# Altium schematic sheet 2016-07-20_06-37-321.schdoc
size 220 x 113 mm; SheetNumber: 1; SheetTotal: 1
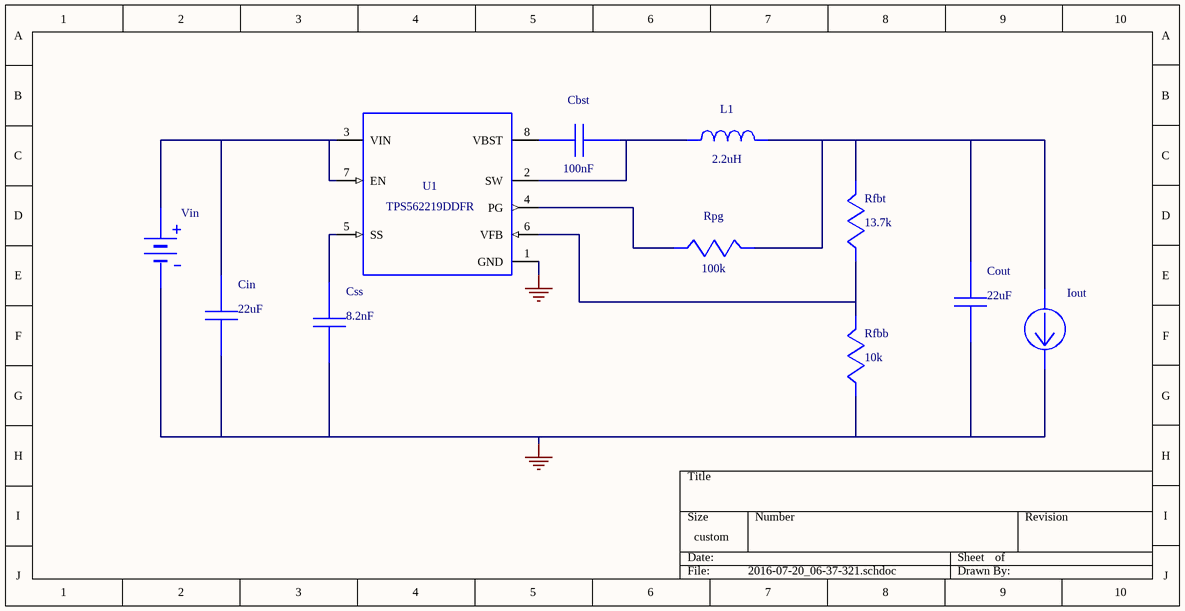
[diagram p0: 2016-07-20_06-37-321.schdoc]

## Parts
Cbst  value 100nF  (hidden comment: 08053C104KAT2A)
Cin  value 22uF  (hidden comment: GRM31CR61A226KE19L)
Cout  value 22uF  (hidden comment: GRM21BC80G226ME39L)
Css  value 8.2nF  (hidden comment: GRM033R61A822KA01D)
Iout  WB_CURRENT_LOAD  (value not drawn)
L1  value 2.2uH  (hidden comment: 'VLF403215MT-2R2M')
Rfbb  value 10k  (hidden comment: CRCW040210K0FKED)
Rfbt  value 13.7k  (hidden comment: CRCW040213K7FKED)
Rpg  value 100k  (hidden comment: CRCW0402100KFKED)
U1  TPS562219DDFR
Vin  WB_BATTERY  (value not drawn)

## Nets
0: Cin.2 Cout.2 Css.2 Iout.2(-) Rfbb.2 U1.1(GND) Vin.2(-)
NetCbst_1: Cbst.1 L1.2 U1.2(SW)
NetCbst_2: Cbst.2 U1.8(VBST)
NetCin_1: Cin.1 U1.3(VIN) U1.7(EN) Vin.1(+)
NetCout_1: Cout.1 Iout.1(+) L1.1 Rfbt.1 Rpg.1
NetCss_1: Css.1 U1.5(SS)
NetRfbb_1: Rfbb.1 Rfbt.2 U1.6(VFB)
NetRpg_2: Rpg.2 U1.4(PG)

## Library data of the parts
Cbst = 08053C104KAT2A: Manufacturer Name: AVX
Cin = GRM31CR61A226KE19L: GRM31CR61A226KE1; Manufacturer Name: MuRata
Cout = GRM21BC80G226ME39L: GRM21BC80G226ME3; Manufacturer Name: MuRata
Css = GRM033R61A822KA01D: GRM033R61A822KA0; Manufacturer Name: MuRata
L1 = 'VLF403215MT-2R2M': VLF403215MT-2R2M; Manufacturer Name: TDK
Rfbb = CRCW040210K0FKED: Manufacturer Name: Vishay-Dale
Rfbt = CRCW040213K7FKED: Manufacturer Name: Vishay-Dale
Rpg = CRCW0402100KFKED: Manufacturer Name: Vishay-Dale
U1 = TPS562219DDFR: Manufacturer Name: Texas Instruments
